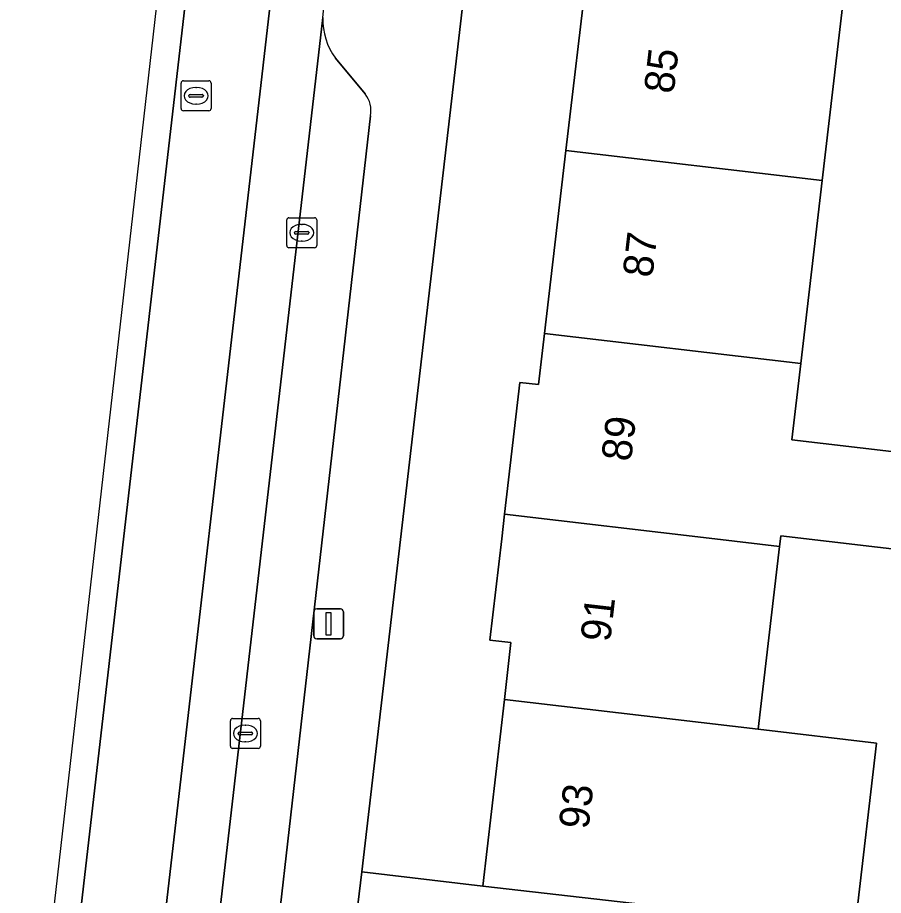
# Model space of a CAD drawing. Extents: x 162250 to 162661, y 380743 to 381606.
# Drawn here: x 162302.6 to 162331.49, y 381238.1 to 381267.39 of the extents above; entities that cross this region are included whole.
import ezdxf

# ---------------------------------------------------------------- set-up
doc = ezdxf.new("R2010")
doc.units = 0
for name, color, linetype in [('IMGEO_Erf', 7, 'Continuous'), ('IMGEO_Kolk', 7, 'Continuous'), ('IMGEO_Lichtmast', 7, 'Continuous'), ('IMGEO_Pand', 7, 'Continuous'), ('IMGEO_Pand_nummerreeks', 7, 'Continuous'), ('IMGEO_Parkeervlak_open', 7, 'Continuous'), ('IMGEO_Rijbaan_lokaal_gesloten', 7, 'Continuous'), ('IMGEO_Rijbaan_lokaal_open', 7, 'Continuous'), ('IMGEO_Rioolput', 7, 'Continuous'), ('IMGEO_Voetpad_open', 7, 'Continuous')]:
    doc.layers.add(name, color=color, linetype=linetype)

msp = doc.modelspace()

# ---------------------------------------------------------------- linework, layer by layer
at = {"layer": 'IMGEO_Erf'}
for points in [[(162326.13, 381342.433), (162314.082, 381238.883), (162318.128, 381238.412), (162318.844, 381244.636), (162319.063, 381246.537), (162318.36, 381246.618), (162318.754, 381250), (162318.85, 381250.823), (162319.362, 381255.221), (162319.98, 381255.148), (162320.18, 381256.854), (162320.896, 381262.957), (162321.612, 381269.061), (162322.328, 381275.164), (162323.044, 381281.267), (162323.76, 381287.37), (162324.476, 381293.474), (162325.192, 381299.577), (162325.922, 381305.8), (162326.655, 381312.052), (162326.794, 381313.238), (162326.763, 381313.242), (162327.389, 381318.581)], [(162330.162, 381268.057), (162329.448, 381261.954), (162328.735, 381255.851), (162328.437, 381253.303), (162336.318, 381252.382)], [(162335.943, 381249.173), (162328.062, 381250.094), (162328.051, 381250), (162328.021, 381249.747), (162327.308, 381243.644), (162331.257, 381243.183), (162330.576, 381237.353), (162326.627, 381237.814), (162326.583, 381237.439), (162337.552, 381235.976)]]:
    msp.add_lwpolyline(points, dxfattribs=at)
at = {"layer": 'IMGEO_Kolk'}
for p, q in [((162311.58, 381259.788), (162311.58, 381260.64)), ((162311.655, 381260.714), (162312.507, 381260.714)), ((162312.581, 381260.64), (162312.581, 381259.788)), ((162312.068, 381260.494), (162312.093, 381260.494)), ((162311.839, 381260.208), (162311.839, 381260.22)), ((162312.277, 381260.171), (162311.879, 381260.171)), ((162311.882, 381260.257), (162312.28, 381260.257)), ((162312.323, 381260.22), (162312.323, 381260.208)), ((162312.091, 381259.934), (162312.066, 381259.934)), ((162312.507, 381259.714), (162311.655, 381259.714)), ((162309.7, 381243.079), (162309.7, 381243.931)), ((162309.775, 381244.005), (162310.627, 381244.005)), ((162310.701, 381243.931), (162310.701, 381243.079)), ((162310.188, 381243.785), (162310.213, 381243.785)), ((162309.959, 381243.499), (162309.959, 381243.511)), ((162310.397, 381243.462), (162309.999, 381243.462)), ((162310.002, 381243.548), (162310.4, 381243.548)), ((162310.443, 381243.511), (162310.443, 381243.499)), ((162310.211, 381243.225), (162310.186, 381243.225)), ((162310.627, 381243.005), (162309.775, 381243.005))]:
    msp.add_line(p, q, dxfattribs=at)
for points in [[(162311.58, 381259.788), (162311.58, 381260.64)], [(162311.655, 381260.714), (162312.507, 381260.714)], [(162312.581, 381260.64), (162312.581, 381259.788)], [(162312.507, 381259.714), (162311.655, 381259.714)], [(162309.7, 381243.079), (162309.7, 381243.931)], [(162309.775, 381244.005), (162310.627, 381244.005)], [(162310.701, 381243.931), (162310.701, 381243.079)], [(162310.627, 381243.005), (162309.775, 381243.005)]]:
    msp.add_lwpolyline(points, dxfattribs=at)
for centre, radius, start, end in [((162311.657, 381260.638), 0.0765, 91.552, 178.448), ((162311.657, 381260.638), 0.0765, 91.552, 178.448), ((162312.505, 381260.638), 0.0765, 1.552, 88.448), ((162312.505, 381260.638), 0.0765, 1.552, 88.448), ((162311.879, 381260.217), 0.0403, 85.8775, 175.7526), ((162311.876, 381260.207), 0.0366, 178.938, 274.7102), ((162312.28, 381260.214), 0.043, 264.8664, 352.4533), ((162312.284, 381260.219), 0.0386, 1.7309, 96.639), ((162311.657, 381259.79), 0.0765, 181.552, 268.448), ((162311.657, 381259.79), 0.0765, 181.552, 268.448), ((162312.505, 381259.79), 0.0765, 271.552, 358.448), ((162312.505, 381259.79), 0.0765, 271.552, 358.448), ((162309.777, 381243.929), 0.0765, 91.552, 178.448), ((162309.777, 381243.929), 0.0765, 91.552, 178.448), ((162310.625, 381243.929), 0.0765, 1.552, 88.448), ((162310.625, 381243.929), 0.0765, 1.552, 88.448), ((162309.999, 381243.508), 0.0403, 85.8775, 175.7526), ((162309.996, 381243.498), 0.0366, 178.938, 274.7102), ((162310.4, 381243.505), 0.043, 264.8664, 352.4533), ((162310.404, 381243.51), 0.0386, 1.7309, 96.639), ((162309.777, 381243.081), 0.0765, 181.552, 268.448), ((162309.777, 381243.081), 0.0765, 181.552, 268.448), ((162310.625, 381243.081), 0.0765, 271.552, 358.448), ((162310.625, 381243.081), 0.0765, 271.552, 358.448)]:
    msp.add_arc(centre, radius, start, end, dxfattribs=at)
for centre, major_axis, ratio, start_param, end_param in [((162312.067, 381260.214), (-0.387, 0.002), 0.722429, 4.712389, 7.853982), ((162312.092, 381260.214), (-0.39, 0.002), 0.717154, 1.570796, 4.712389), ((162310.187, 381243.505), (-0.387, 0.002), 0.722429, 4.712389, 7.853982), ((162310.212, 381243.505), (-0.39, 0.002), 0.717154, 1.570796, 4.712389)]:
    msp.add_ellipse(centre, major_axis=major_axis, ratio=ratio, start_param=start_param, end_param=end_param, dxfattribs=at)
at = {"layer": 'IMGEO_Lichtmast'}
for p, q in [((162312.479, 381246.763), (162312.479, 381247.563)), ((162312.479, 381247.563), (162312.479, 381246.763)), ((162312.579, 381247.663), (162313.369, 381247.663)), ((162313.369, 381247.663), (162312.579, 381247.663)), ((162313.469, 381247.563), (162313.469, 381246.763)), ((162313.469, 381246.763), (162313.469, 381247.563)), ((162313.369, 381246.663), (162312.579, 381246.663)), ((162312.579, 381246.663), (162313.369, 381246.663))]:
    msp.add_line(p, q, dxfattribs=at)
msp.add_lwpolyline([(162312.899, 381247.538), (162313.049, 381247.538), (162313.049, 381246.788), (162312.899, 381246.788), (162312.899, 381247.538)], dxfattribs=at)
for centre, start, end in [((162312.579, 381247.563), 90, 180), ((162312.579, 381247.563), 90, 180), ((162313.369, 381247.563), 0, 90), ((162313.369, 381247.563), 360, 90), ((162312.579, 381246.763), 180, 270), ((162312.579, 381246.763), 180, 270), ((162313.369, 381246.763), 270, 0), ((162313.369, 381246.763), 270, 0)]:
    msp.add_arc(centre, 0.1, start, end, dxfattribs=at)
at = {"layer": 'IMGEO_Pand'}
for points in [[(162321.612, 381269.061), (162320.896, 381262.957), (162329.448, 381261.954), (162330.162, 381268.057)], [(162328.735, 381255.851), (162329.448, 381261.954), (162320.896, 381262.957), (162320.18, 381256.854)], [(162328.437, 381253.303), (162328.735, 381255.851), (162320.18, 381256.854), (162319.98, 381255.148), (162319.362, 381255.221), (162318.85, 381250.823), (162325.864, 381250), (162328.021, 381249.747), (162328.051, 381250), (162328.062, 381250.094), (162335.943, 381249.173), (162336.318, 381252.382)], [(162327.308, 381243.644), (162328.021, 381249.747), (162325.864, 381250), (162318.85, 381250.823), (162318.754, 381250), (162318.36, 381246.618), (162319.063, 381246.537), (162318.844, 381244.636)], [(162327.308, 381243.644), (162318.844, 381244.636), (162318.128, 381238.412), (162323.096, 381237.84), (162326.583, 381237.439), (162326.627, 381237.814), (162330.576, 381237.353), (162331.257, 381243.183)]]:
    msp.add_lwpolyline(points, close=True, dxfattribs=at)
at = {"layer": 'IMGEO_Parkeervlak_open'}
for points in [[(162312.784, 381267.394), (162308.157, 381227.247)], [(162314.2, 381264.844), (162313.202, 381266.034)], [(162310.526, 381230.348), (162314.376, 381264.117)]]:
    msp.add_lwpolyline(points, dxfattribs=at)
for centre, radius, start, end in [((162315.021, 381267.337), 2.238, 178.5485, 215.6215), ((162313.457, 381264.279), 0.933, 349.9836, 37.2343)]:
    msp.add_arc(centre, radius, start, end, dxfattribs=at)
at = {"layer": 'IMGEO_Rijbaan_lokaal_gesloten'}
for points in [[(162318.31, 381360.535), (162315.97, 381344.552), (162303.714, 381236.926), (162302.598, 381226.919), (162303.468, 381226.833), (162318.873, 381360.48)], [(162318.256, 381314.678), (162318.523, 381317.019), (162321.484, 381342.938), (162321.621, 381344.181), (162323.053, 381356.29), (162323.469, 381359.935), (162321.674, 381360.143), (162306.264, 381226.555), (162307.997, 381226.383), (162308.085, 381226.743), (162308.157, 381227.247), (162312.784, 381267.394), (162312.897, 381268.512)]]:
    msp.add_lwpolyline(points, close=True, dxfattribs=at)
at = {"layer": 'IMGEO_Rijbaan_lokaal_open'}
msp.add_lwpolyline([(162321.674, 381360.143), (162318.873, 381360.48), (162303.468, 381226.833), (162306.264, 381226.555)], close=True, dxfattribs=at)
at = {"layer": 'IMGEO_Rioolput'}
for p, q in [((162308.131, 381265.284), (162308.983, 381265.284)), ((162308.056, 381264.358), (162308.056, 381265.21)), ((162308.544, 381265.064), (162308.569, 381265.064)), ((162309.057, 381265.21), (162309.057, 381264.358)), ((162308.315, 381264.778), (162308.315, 381264.79)), ((162308.753, 381264.741), (162308.355, 381264.741)), ((162308.358, 381264.827), (162308.756, 381264.827)), ((162308.799, 381264.79), (162308.799, 381264.778)), ((162308.567, 381264.504), (162308.542, 381264.504)), ((162308.983, 381264.284), (162308.131, 381264.284))]:
    msp.add_line(p, q, dxfattribs=at)
for points in [[(162308.131, 381265.284), (162308.983, 381265.284)], [(162308.056, 381264.358), (162308.056, 381265.21)], [(162309.057, 381265.21), (162309.057, 381264.358)], [(162308.983, 381264.284), (162308.131, 381264.284)]]:
    msp.add_lwpolyline(points, dxfattribs=at)
for centre, radius, start, end in [((162308.133, 381265.208), 0.0765, 91.552, 178.448), ((162308.133, 381265.208), 0.0765, 91.552, 178.448), ((162308.981, 381265.208), 0.0765, 1.552, 88.448), ((162308.981, 381265.208), 0.0765, 1.552, 88.448), ((162308.355, 381264.787), 0.0403, 85.8775, 175.7526), ((162308.352, 381264.777), 0.0366, 178.938, 274.7102), ((162308.756, 381264.784), 0.043, 264.8664, 352.4533), ((162308.76, 381264.789), 0.0386, 1.7309, 96.639), ((162308.133, 381264.36), 0.0765, 181.552, 268.448), ((162308.133, 381264.36), 0.0765, 181.552, 268.448), ((162308.981, 381264.36), 0.0765, 271.552, 358.448), ((162308.981, 381264.36), 0.0765, 271.552, 358.448)]:
    msp.add_arc(centre, radius, start, end, dxfattribs=at)
for centre, major_axis, ratio, start_param, end_param in [((162308.543, 381264.784), (-0.387, 0.002), 0.722429, 4.712389, 7.853982), ((162308.568, 381264.784), (-0.39, 0.002), 0.717154, 1.570796, 4.712389)]:
    msp.add_ellipse(centre, major_axis=major_axis, ratio=ratio, start_param=start_param, end_param=end_param, dxfattribs=at)
at = {"layer": 'IMGEO_Voetpad_open'}
for points in [[(162313.954, 381237.787), (162314.082, 381238.883), (162326.13, 381342.433), (162327.527, 381354.554), (162328.382, 381362.452), (162328.733, 381365.93)], [(162313.202, 381266.034), (162314.2, 381264.844)], [(162314.376, 381264.117), (162310.526, 381230.348)], [(162337.552, 381235.976), (162326.583, 381237.439), (162323.096, 381237.84), (162318.128, 381238.412), (162314.082, 381238.883), (162313.954, 381237.787), (162316.962, 381237.437), (162321.929, 381236.86), (162322.465, 381236.798), (162324.594, 381236.551), (162324.499, 381235.73), (162328.022, 381235.269), (162333.401, 381234.577)]]:
    msp.add_lwpolyline(points, dxfattribs=at)
for centre, radius, start, end in [((162315.021, 381267.337), 2.238, 178.5485, 215.6215), ((162313.457, 381264.279), 0.933, 349.9836, 37.2343)]:
    msp.add_arc(centre, radius, start, end, dxfattribs=at)

# ---------------------------------------------------------------- texts
at = {"layer": 'IMGEO_Pand_nummerreeks'}
for s, rotation, p in [('85', 83.395, (162324.488, 381264.828)), ('87', 83.395, (162323.778, 381258.692)), ('89', 83.394, (162323.067, 381252.555)), ('91', 83.395, (162322.37, 381246.531)), ('93', 83.394, (162321.646, 381240.282))]:
    msp.add_text(s, height=1, rotation=rotation, dxfattribs=at).set_placement(p)

doc.saveas('drawing.dxf')
